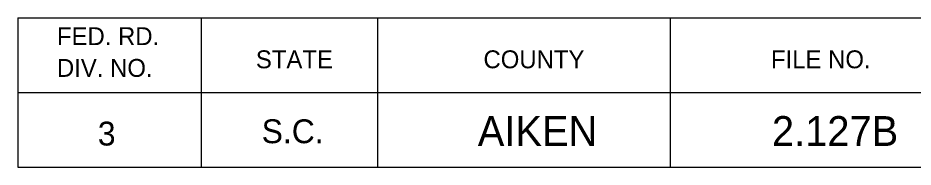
# Model space of a CAD drawing. Extents: x 1000 to 1162, y 999 to 8520.
# Drawn here: x 1133.06 to 1148.08, y 4895.05 to 4897.55 of the extents above; entities that cross this region are included whole.
import ezdxf

# ---------------------------------------------------------------- set-up
doc = ezdxf.new("R2010")
doc.units = 0
doc.layers.add('Level 20', color=7, linetype='Continuous')
doc.layers.add('Level 3', color=7, linetype='Continuous')

msp = doc.modelspace()

# ---------------------------------------------------------------- linework, layer by layer
at = {"layer": 'Level 3'}
for p, q in [((1133.055, 4897.546), (1161.555, 4897.546)), ((1133.055, 4897.546), (1133.055, 4895.046)), ((1133.055, 4897.546), (1161.555, 4897.546)), ((1133.055, 4897.546), (1133.055, 4895.046)), ((1133.055, 4897.546), (1161.555, 4897.546)), ((1133.055, 4897.546), (1133.055, 4895.046)), ((1133.055, 4897.546), (1161.555, 4897.546)), ((1133.055, 4897.546), (1133.055, 4895.046)), ((1133.055, 4897.546), (1161.555, 4897.546)), ((1133.055, 4897.546), (1133.055, 4895.046)), ((1133.055, 4897.546), (1161.555, 4897.546)), ((1133.055, 4897.546), (1133.055, 4895.046)), ((1133.055, 4897.546), (1161.555, 4897.546)), ((1133.055, 4897.546), (1133.055, 4895.046)), ((1133.055, 4897.546), (1161.555, 4897.546)), ((1133.055, 4897.546), (1133.055, 4895.046)), ((1133.055, 4897.546), (1161.555, 4897.546)), ((1133.055, 4897.546), (1133.055, 4895.046)), ((1133.055, 4897.546), (1161.555, 4897.546)), ((1133.055, 4897.546), (1133.055, 4895.046)), ((1133.055, 4897.546), (1161.555, 4897.546)), ((1133.055, 4897.546), (1133.055, 4895.046)), ((1133.055, 4897.546), (1161.555, 4897.546)), ((1133.055, 4897.546), (1133.055, 4895.046)), ((1133.055, 4897.546), (1161.555, 4897.546)), ((1133.055, 4897.546), (1133.055, 4895.046)), ((1133.055, 4897.546), (1161.555, 4897.546)), ((1133.055, 4897.546), (1133.055, 4895.046)), ((1133.055, 4897.546), (1161.555, 4897.546)), ((1133.055, 4897.546), (1133.055, 4895.046)), ((1133.055, 4897.546), (1161.555, 4897.546)), ((1133.055, 4897.546), (1133.055, 4895.046)), ((1133.055, 4897.546), (1161.555, 4897.546)), ((1133.055, 4897.546), (1133.055, 4895.046)), ((1133.055, 4897.546), (1161.555, 4897.546)), ((1133.055, 4897.546), (1133.055, 4895.046)), ((1133.055, 4897.546), (1161.555, 4897.546)), ((1133.055, 4897.546), (1133.055, 4895.046)), ((1133.055, 4897.546), (1161.555, 4897.546)), ((1133.055, 4897.546), (1133.055, 4895.046)), ((1133.055, 4897.546), (1161.555, 4897.546)), ((1133.055, 4897.546), (1133.055, 4895.046)), ((1133.055, 4897.546), (1161.555, 4897.546)), ((1133.055, 4897.546), (1133.055, 4895.046)), ((1133.055, 4897.546), (1161.555, 4897.546)), ((1133.055, 4897.546), (1133.055, 4895.046)), ((1133.055, 4897.546), (1161.555, 4897.546)), ((1133.055, 4897.546), (1133.055, 4895.046)), ((1133.055, 4897.546), (1161.555, 4897.546)), ((1133.055, 4897.546), (1133.055, 4895.046)), ((1133.055, 4897.546), (1161.555, 4897.546)), ((1133.055, 4897.546), (1133.055, 4895.046)), ((1133.055, 4897.546), (1161.555, 4897.546)), ((1133.055, 4897.546), (1133.055, 4895.046)), ((1133.055, 4897.546), (1161.555, 4897.546)), ((1133.055, 4897.546), (1133.055, 4895.046)), ((1133.055, 4897.546), (1161.555, 4897.546)), ((1133.055, 4897.546), (1133.055, 4895.046)), ((1133.055, 4897.546), (1161.555, 4897.546)), ((1133.055, 4897.546), (1133.055, 4895.046)), ((1133.055, 4897.546), (1161.555, 4897.546)), ((1133.055, 4897.546), (1133.055, 4895.046)), ((1133.055, 4897.546), (1161.555, 4897.546)), ((1133.055, 4897.546), (1133.055, 4895.046)), ((1136.132, 4897.546), (1136.132, 4895.046)), ((1136.132, 4897.546), (1136.132, 4895.046)), ((1136.132, 4897.546), (1136.132, 4895.046)), ((1136.132, 4897.546), (1136.132, 4895.046)), ((1136.132, 4897.546), (1136.132, 4895.046)), ((1136.132, 4897.546), (1136.132, 4895.046)), ((1136.132, 4897.546), (1136.132, 4895.046)), ((1136.132, 4897.546), (1136.132, 4895.046)), ((1136.132, 4897.546), (1136.132, 4895.046)), ((1136.132, 4897.546), (1136.132, 4895.046)), ((1136.132, 4897.546), (1136.132, 4895.046)), ((1136.132, 4897.546), (1136.132, 4895.046)), ((1136.132, 4897.546), (1136.132, 4895.046)), ((1136.132, 4897.546), (1136.132, 4895.046)), ((1136.132, 4897.546), (1136.132, 4895.046)), ((1136.132, 4897.546), (1136.132, 4895.046)), ((1136.132, 4897.546), (1136.132, 4895.046)), ((1136.132, 4897.546), (1136.132, 4895.046)), ((1136.132, 4897.546), (1136.132, 4895.046)), ((1136.132, 4897.546), (1136.132, 4895.046)), ((1136.132, 4897.546), (1136.132, 4895.046)), ((1136.132, 4897.546), (1136.132, 4895.046)), ((1136.132, 4897.546), (1136.132, 4895.046)), ((1136.132, 4897.546), (1136.132, 4895.046)), ((1136.132, 4897.546), (1136.132, 4895.046)), ((1136.132, 4897.546), (1136.132, 4895.046)), ((1136.132, 4897.546), (1136.132, 4895.046)), ((1136.132, 4897.546), (1136.132, 4895.046)), ((1136.132, 4897.546), (1136.132, 4895.046)), ((1136.132, 4897.546), (1136.132, 4895.046)), ((1136.132, 4897.546), (1136.132, 4895.046)), ((1136.132, 4897.546), (1136.132, 4895.046)), ((1139.087, 4897.546), (1139.087, 4895.046)), ((1139.087, 4897.546), (1139.087, 4895.046)), ((1139.087, 4897.546), (1139.087, 4895.046)), ((1139.087, 4897.546), (1139.087, 4895.046)), ((1139.087, 4897.546), (1139.087, 4895.046)), ((1139.087, 4897.546), (1139.087, 4895.046)), ((1139.087, 4897.546), (1139.087, 4895.046)), ((1139.087, 4897.546), (1139.087, 4895.046)), ((1139.087, 4897.546), (1139.087, 4895.046)), ((1139.087, 4897.546), (1139.087, 4895.046)), ((1139.087, 4897.546), (1139.087, 4895.046)), ((1139.087, 4897.546), (1139.087, 4895.046)), ((1139.087, 4897.546), (1139.087, 4895.046)), ((1139.087, 4897.546), (1139.087, 4895.046)), ((1139.087, 4897.546), (1139.087, 4895.046)), ((1139.087, 4897.546), (1139.087, 4895.046)), ((1139.087, 4897.546), (1139.087, 4895.046)), ((1139.087, 4897.546), (1139.087, 4895.046)), ((1139.087, 4897.546), (1139.087, 4895.046)), ((1139.087, 4897.546), (1139.087, 4895.046)), ((1139.087, 4897.546), (1139.087, 4895.046)), ((1139.087, 4897.546), (1139.087, 4895.046)), ((1139.087, 4897.546), (1139.087, 4895.046)), ((1139.087, 4897.546), (1139.087, 4895.046)), ((1139.087, 4897.546), (1139.087, 4895.046)), ((1139.087, 4897.546), (1139.087, 4895.046)), ((1139.087, 4897.546), (1139.087, 4895.046)), ((1139.087, 4897.546), (1139.087, 4895.046)), ((1139.087, 4897.546), (1139.087, 4895.046)), ((1139.087, 4897.546), (1139.087, 4895.046)), ((1139.087, 4897.546), (1139.087, 4895.046)), ((1139.087, 4897.546), (1139.087, 4895.046)), ((1144, 4897.546), (1144, 4895.046)), ((1144, 4897.546), (1144, 4895.046)), ((1144, 4897.546), (1144, 4895.046)), ((1144, 4897.546), (1144, 4895.046)), ((1144, 4897.546), (1144, 4895.046)), ((1144, 4897.546), (1144, 4895.046)), ((1144, 4897.546), (1144, 4895.046)), ((1144, 4897.546), (1144, 4895.046)), ((1144, 4897.546), (1144, 4895.046)), ((1144, 4897.546), (1144, 4895.046)), ((1144, 4897.546), (1144, 4895.046)), ((1144, 4897.546), (1144, 4895.046)), ((1144, 4897.546), (1144, 4895.046)), ((1144, 4897.546), (1144, 4895.046)), ((1144, 4897.546), (1144, 4895.046)), ((1144, 4897.546), (1144, 4895.046)), ((1144, 4897.546), (1144, 4895.046)), ((1144, 4897.546), (1144, 4895.046)), ((1144, 4897.546), (1144, 4895.046)), ((1144, 4897.546), (1144, 4895.046)), ((1144, 4897.546), (1144, 4895.046)), ((1144, 4897.546), (1144, 4895.046)), ((1144, 4897.546), (1144, 4895.046)), ((1144, 4897.546), (1144, 4895.046)), ((1144, 4897.546), (1144, 4895.046)), ((1144, 4897.546), (1144, 4895.046)), ((1144, 4897.546), (1144, 4895.046)), ((1144, 4897.546), (1144, 4895.046)), ((1144, 4897.546), (1144, 4895.046)), ((1144, 4897.546), (1144, 4895.046)), ((1144, 4897.546), (1144, 4895.046)), ((1144, 4897.546), (1144, 4895.046)), ((1133.055, 4896.296), (1161.555, 4896.296)), ((1133.055, 4896.296), (1161.555, 4896.296)), ((1133.055, 4896.296), (1161.555, 4896.296)), ((1133.055, 4896.296), (1161.555, 4896.296)), ((1133.055, 4896.296), (1161.555, 4896.296)), ((1133.055, 4896.296), (1161.555, 4896.296)), ((1133.055, 4896.296), (1161.555, 4896.296)), ((1133.055, 4896.296), (1161.555, 4896.296)), ((1133.055, 4896.296), (1161.555, 4896.296)), ((1133.055, 4896.296), (1161.555, 4896.296)), ((1133.055, 4896.296), (1161.555, 4896.296)), ((1133.055, 4896.296), (1161.555, 4896.296)), ((1133.055, 4896.296), (1161.555, 4896.296)), ((1133.055, 4896.296), (1161.555, 4896.296)), ((1133.055, 4896.296), (1161.555, 4896.296)), ((1133.055, 4896.296), (1161.555, 4896.296)), ((1133.055, 4896.296), (1161.555, 4896.296)), ((1133.055, 4896.296), (1161.555, 4896.296)), ((1133.055, 4896.296), (1161.555, 4896.296)), ((1133.055, 4896.296), (1161.555, 4896.296)), ((1133.055, 4896.296), (1161.555, 4896.296)), ((1133.055, 4896.296), (1161.555, 4896.296)), ((1133.055, 4896.296), (1161.555, 4896.296)), ((1133.055, 4896.296), (1161.555, 4896.296)), ((1133.055, 4896.296), (1161.555, 4896.296)), ((1133.055, 4896.296), (1161.555, 4896.296)), ((1133.055, 4896.296), (1161.555, 4896.296)), ((1133.055, 4896.296), (1161.555, 4896.296)), ((1133.055, 4896.296), (1161.555, 4896.296)), ((1133.055, 4896.296), (1161.555, 4896.296)), ((1133.055, 4896.296), (1161.555, 4896.296)), ((1133.055, 4896.296), (1161.555, 4896.296)), ((1133.055, 4895.046), (1161.555, 4895.046)), ((1133.055, 4895.046), (1161.555, 4895.046)), ((1133.055, 4895.046), (1161.555, 4895.046)), ((1133.055, 4895.046), (1161.555, 4895.046)), ((1133.055, 4895.046), (1161.555, 4895.046)), ((1133.055, 4895.046), (1161.555, 4895.046)), ((1133.055, 4895.046), (1161.555, 4895.046)), ((1133.055, 4895.046), (1161.555, 4895.046)), ((1133.055, 4895.046), (1161.555, 4895.046)), ((1133.055, 4895.046), (1161.555, 4895.046)), ((1133.055, 4895.046), (1161.555, 4895.046)), ((1133.055, 4895.046), (1161.555, 4895.046)), ((1133.055, 4895.046), (1161.555, 4895.046)), ((1133.055, 4895.046), (1161.555, 4895.046)), ((1133.055, 4895.046), (1161.555, 4895.046)), ((1133.055, 4895.046), (1161.555, 4895.046)), ((1133.055, 4895.046), (1161.555, 4895.046)), ((1133.055, 4895.046), (1161.555, 4895.046)), ((1133.055, 4895.046), (1161.555, 4895.046)), ((1133.055, 4895.046), (1161.555, 4895.046)), ((1133.055, 4895.046), (1161.555, 4895.046)), ((1133.055, 4895.046), (1161.555, 4895.046)), ((1133.055, 4895.046), (1161.555, 4895.046)), ((1133.055, 4895.046), (1161.555, 4895.046)), ((1133.055, 4895.046), (1161.555, 4895.046)), ((1133.055, 4895.046), (1161.555, 4895.046)), ((1133.055, 4895.046), (1161.555, 4895.046)), ((1133.055, 4895.046), (1161.555, 4895.046)), ((1133.055, 4895.046), (1161.555, 4895.046)), ((1133.055, 4895.046), (1161.555, 4895.046)), ((1133.055, 4895.046), (1161.555, 4895.046)), ((1133.055, 4895.046), (1161.555, 4895.046))]:
    msp.add_line(p, q, dxfattribs=at)

# ---------------------------------------------------------------- texts
at = {"layer": 'Level 20'}
for s, p in [('AIKEN', (1140.771, 4895.4)), ('2.127B', (1145.707, 4895.4))]:
    msp.add_text(s, height=0.5, dxfattribs=at).set_placement(p)
at = {"layer": 'Level 3'}
for s, height, p in [('FED. RD.', 0.3, (1133.71, 4897.09)), ('FED. RD.', 0.3, (1133.71, 4897.09)), ('FED. RD.', 0.3, (1133.71, 4897.09)), ('FED. RD.', 0.3, (1133.71, 4897.09)), ('FED. RD.', 0.3, (1133.71, 4897.09)), ('FED. RD.', 0.3, (1133.71, 4897.09)), ('FED. RD.', 0.3, (1133.71, 4897.09)), ('FED. RD.', 0.3, (1133.71, 4897.09)), ('FED. RD.', 0.3, (1133.71, 4897.09)), ('FED. RD.', 0.3, (1133.71, 4897.09)), ('FED. RD.', 0.3, (1133.71, 4897.09)), ('FED. RD.', 0.3, (1133.71, 4897.09)), ('FED. RD.', 0.3, (1133.71, 4897.09)), ('FED. RD.', 0.3, (1133.71, 4897.09)), ('FED. RD.', 0.3, (1133.71, 4897.09)), ('FED. RD.', 0.3, (1133.71, 4897.09)), ('FED. RD.', 0.3, (1133.71, 4897.09)), ('FED. RD.', 0.3, (1133.71, 4897.09)), ('FED. RD.', 0.3, (1133.71, 4897.09)), ('FED. RD.', 0.3, (1133.71, 4897.09)), ('FED. RD.', 0.3, (1133.71, 4897.09)), ('FED. RD.', 0.3, (1133.71, 4897.09)), ('FED. RD.', 0.3, (1133.71, 4897.09)), ('FED. RD.', 0.3, (1133.71, 4897.09)), ('FED. RD.', 0.3, (1133.71, 4897.09)), ('FED. RD.', 0.3, (1133.71, 4897.09)), ('FED. RD.', 0.3, (1133.71, 4897.09)), ('FED. RD.', 0.3, (1133.71, 4897.09)), ('FED. RD.', 0.3, (1133.71, 4897.09)), ('FED. RD.', 0.3, (1133.71, 4897.09)), ('FED. RD.', 0.3, (1133.71, 4897.09)), ('FED. RD.', 0.3, (1133.71, 4897.09)), ('STATE', 0.3, (1137.048, 4896.702)), ('STATE', 0.3, (1137.048, 4896.702)), ('STATE', 0.3, (1137.048, 4896.702)), ('STATE', 0.3, (1137.048, 4896.702)), ('STATE', 0.3, (1137.048, 4896.702)), ('STATE', 0.3, (1137.048, 4896.702)), ('STATE', 0.3, (1137.048, 4896.702)), ('STATE', 0.3, (1137.048, 4896.702)), ('STATE', 0.3, (1137.048, 4896.702)), ('STATE', 0.3, (1137.048, 4896.702)), ('STATE', 0.3, (1137.048, 4896.702)), ('STATE', 0.3, (1137.048, 4896.702)), ('STATE', 0.3, (1137.048, 4896.702)), ('STATE', 0.3, (1137.048, 4896.702)), ('STATE', 0.3, (1137.048, 4896.702)), ('STATE', 0.3, (1137.048, 4896.702)), ('STATE', 0.3, (1137.048, 4896.702)), ('STATE', 0.3, (1137.048, 4896.702)), ('STATE', 0.3, (1137.048, 4896.702)), ('STATE', 0.3, (1137.048, 4896.702)), ('STATE', 0.3, (1137.048, 4896.702)), ('STATE', 0.3, (1137.048, 4896.702)), ('STATE', 0.3, (1137.048, 4896.702)), ('STATE', 0.3, (1137.048, 4896.702)), ('STATE', 0.3, (1137.048, 4896.702)), ('STATE', 0.3, (1137.048, 4896.702)), ('STATE', 0.3, (1137.048, 4896.702)), ('STATE', 0.3, (1137.048, 4896.702)), ('STATE', 0.3, (1137.048, 4896.702)), ('STATE', 0.3, (1137.048, 4896.702)), ('STATE', 0.3, (1137.048, 4896.702)), ('STATE', 0.3, (1137.048, 4896.702)), ('COUNTY', 0.3, (1140.867, 4896.702)), ('COUNTY', 0.3, (1140.867, 4896.702)), ('COUNTY', 0.3, (1140.867, 4896.702)), ('COUNTY', 0.3, (1140.867, 4896.702)), ('COUNTY', 0.3, (1140.867, 4896.702)), ('COUNTY', 0.3, (1140.867, 4896.702)), ('COUNTY', 0.3, (1140.867, 4896.702)), ('COUNTY', 0.3, (1140.867, 4896.702)), ('COUNTY', 0.3, (1140.867, 4896.702)), ('COUNTY', 0.3, (1140.867, 4896.702)), ('COUNTY', 0.3, (1140.867, 4896.702)), ('COUNTY', 0.3, (1140.867, 4896.702)), ('COUNTY', 0.3, (1140.867, 4896.702)), ('COUNTY', 0.3, (1140.867, 4896.702)), ('COUNTY', 0.3, (1140.867, 4896.702)), ('COUNTY', 0.3, (1140.867, 4896.702)), ('COUNTY', 0.3, (1140.867, 4896.702)), ('COUNTY', 0.3, (1140.867, 4896.702)), ('COUNTY', 0.3, (1140.867, 4896.702)), ('COUNTY', 0.3, (1140.867, 4896.702)), ('COUNTY', 0.3, (1140.867, 4896.702)), ('COUNTY', 0.3, (1140.867, 4896.702)), ('COUNTY', 0.3, (1140.867, 4896.702)), ('COUNTY', 0.3, (1140.867, 4896.702)), ('COUNTY', 0.3, (1140.867, 4896.702)), ('COUNTY', 0.3, (1140.867, 4896.702)), ('COUNTY', 0.3, (1140.867, 4896.702)), ('COUNTY', 0.3, (1140.867, 4896.702)), ('COUNTY', 0.3, (1140.867, 4896.702)), ('COUNTY', 0.3, (1140.867, 4896.702)), ('COUNTY', 0.3, (1140.867, 4896.702)), ('COUNTY', 0.3, (1140.867, 4896.702)), ('FILE NO.', 0.3, (1145.691, 4896.702)), ('FILE NO.', 0.3, (1145.691, 4896.702)), ('FILE NO.', 0.3, (1145.691, 4896.702)), ('FILE NO.', 0.3, (1145.691, 4896.702)), ('FILE NO.', 0.3, (1145.691, 4896.702)), ('FILE NO.', 0.3, (1145.691, 4896.702)), ('FILE NO.', 0.3, (1145.691, 4896.702)), ('FILE NO.', 0.3, (1145.691, 4896.702)), ('FILE NO.', 0.3, (1145.691, 4896.702)), ('FILE NO.', 0.3, (1145.691, 4896.702)), ('FILE NO.', 0.3, (1145.691, 4896.702)), ('FILE NO.', 0.3, (1145.691, 4896.702)), ('FILE NO.', 0.3, (1145.691, 4896.702)), ('FILE NO.', 0.3, (1145.691, 4896.702)), ('FILE NO.', 0.3, (1145.691, 4896.702)), ('FILE NO.', 0.3, (1145.691, 4896.702)), ('FILE NO.', 0.3, (1145.691, 4896.702)), ('FILE NO.', 0.3, (1145.691, 4896.702)), ('FILE NO.', 0.3, (1145.691, 4896.702)), ('FILE NO.', 0.3, (1145.691, 4896.702)), ('FILE NO.', 0.3, (1145.691, 4896.702)), ('FILE NO.', 0.3, (1145.691, 4896.702)), ('FILE NO.', 0.3, (1145.691, 4896.702)), ('FILE NO.', 0.3, (1145.691, 4896.702)), ('FILE NO.', 0.3, (1145.691, 4896.702)), ('FILE NO.', 0.3, (1145.691, 4896.702)), ('FILE NO.', 0.3, (1145.691, 4896.702)), ('FILE NO.', 0.3, (1145.691, 4896.702)), ('FILE NO.', 0.3, (1145.691, 4896.702)), ('FILE NO.', 0.3, (1145.691, 4896.702)), ('FILE NO.', 0.3, (1145.691, 4896.702)), ('FILE NO.', 0.3, (1145.691, 4896.702)), ('DIV. NO.', 0.3, (1133.71, 4896.558)), ('DIV. NO.', 0.3, (1133.71, 4896.558)), ('DIV. NO.', 0.3, (1133.71, 4896.558)), ('DIV. NO.', 0.3, (1133.71, 4896.558)), ('DIV. NO.', 0.3, (1133.71, 4896.558)), ('DIV. NO.', 0.3, (1133.71, 4896.558)), ('DIV. NO.', 0.3, (1133.71, 4896.558)), ('DIV. NO.', 0.3, (1133.71, 4896.558)), ('DIV. NO.', 0.3, (1133.71, 4896.558)), ('DIV. NO.', 0.3, (1133.71, 4896.558)), ('DIV. NO.', 0.3, (1133.71, 4896.558)), ('DIV. NO.', 0.3, (1133.71, 4896.558)), ('DIV. NO.', 0.3, (1133.71, 4896.558)), ('DIV. NO.', 0.3, (1133.71, 4896.558)), ('DIV. NO.', 0.3, (1133.71, 4896.558)), ('DIV. NO.', 0.3, (1133.71, 4896.558)), ('DIV. NO.', 0.3, (1133.71, 4896.558)), ('DIV. NO.', 0.3, (1133.71, 4896.558)), ('DIV. NO.', 0.3, (1133.71, 4896.558)), ('DIV. NO.', 0.3, (1133.71, 4896.558)), ('DIV. NO.', 0.3, (1133.71, 4896.558)), ('DIV. NO.', 0.3, (1133.71, 4896.558)), ('DIV. NO.', 0.3, (1133.71, 4896.558)), ('DIV. NO.', 0.3, (1133.71, 4896.558)), ('DIV. NO.', 0.3, (1133.71, 4896.558)), ('DIV. NO.', 0.3, (1133.71, 4896.558)), ('DIV. NO.', 0.3, (1133.71, 4896.558)), ('DIV. NO.', 0.3, (1133.71, 4896.558)), ('DIV. NO.', 0.3, (1133.71, 4896.558)), ('DIV. NO.', 0.3, (1133.71, 4896.558)), ('DIV. NO.', 0.3, (1133.71, 4896.558)), ('DIV. NO.', 0.3, (1133.71, 4896.558)), ('S.C.', 0.4, (1137.145, 4895.446)), ('S.C.', 0.4, (1137.145, 4895.446)), ('S.C.', 0.4, (1137.145, 4895.446)), ('S.C.', 0.4, (1137.145, 4895.446)), ('S.C.', 0.4, (1137.145, 4895.446)), ('S.C.', 0.4, (1137.145, 4895.446)), ('S.C.', 0.4, (1137.145, 4895.446)), ('S.C.', 0.4, (1137.145, 4895.446)), ('S.C.', 0.4, (1137.145, 4895.446)), ('S.C.', 0.4, (1137.145, 4895.446)), ('S.C.', 0.4, (1137.145, 4895.446)), ('S.C.', 0.4, (1137.145, 4895.446)), ('S.C.', 0.4, (1137.145, 4895.446)), ('S.C.', 0.4, (1137.145, 4895.446)), ('S.C.', 0.4, (1137.145, 4895.446)), ('S.C.', 0.4, (1137.145, 4895.446)), ('S.C.', 0.4, (1137.145, 4895.446)), ('S.C.', 0.4, (1137.145, 4895.446)), ('S.C.', 0.4, (1137.145, 4895.446)), ('S.C.', 0.4, (1137.145, 4895.446)), ('S.C.', 0.4, (1137.145, 4895.446)), ('S.C.', 0.4, (1137.145, 4895.446)), ('S.C.', 0.4, (1137.145, 4895.446)), ('S.C.', 0.4, (1137.145, 4895.446)), ('S.C.', 0.4, (1137.145, 4895.446)), ('S.C.', 0.4, (1137.145, 4895.446)), ('S.C.', 0.4, (1137.145, 4895.446)), ('S.C.', 0.4, (1137.145, 4895.446)), ('S.C.', 0.4, (1137.145, 4895.446)), ('S.C.', 0.4, (1137.145, 4895.446)), ('S.C.', 0.4, (1137.145, 4895.446)), ('S.C.', 0.4, (1137.145, 4895.446)), ('3', 0.4, (1134.396, 4895.407)), ('3', 0.4, (1134.396, 4895.407)), ('3', 0.4, (1134.396, 4895.407)), ('3', 0.4, (1134.396, 4895.407)), ('3', 0.4, (1134.396, 4895.407)), ('3', 0.4, (1134.396, 4895.407)), ('3', 0.4, (1134.396, 4895.407)), ('3', 0.4, (1134.396, 4895.407)), ('3', 0.4, (1134.396, 4895.407)), ('3', 0.4, (1134.396, 4895.407)), ('3', 0.4, (1134.396, 4895.407)), ('3', 0.4, (1134.396, 4895.407)), ('3', 0.4, (1134.396, 4895.407)), ('3', 0.4, (1134.396, 4895.407)), ('3', 0.4, (1134.396, 4895.407)), ('3', 0.4, (1134.396, 4895.407)), ('3', 0.4, (1134.396, 4895.407)), ('3', 0.4, (1134.396, 4895.407)), ('3', 0.4, (1134.396, 4895.407)), ('3', 0.4, (1134.396, 4895.407)), ('3', 0.4, (1134.396, 4895.407)), ('3', 0.4, (1134.396, 4895.407)), ('3', 0.4, (1134.396, 4895.407)), ('3', 0.4, (1134.396, 4895.407)), ('3', 0.4, (1134.396, 4895.407)), ('3', 0.4, (1134.396, 4895.407)), ('3', 0.4, (1134.396, 4895.407)), ('3', 0.4, (1134.396, 4895.407)), ('3', 0.4, (1134.396, 4895.407)), ('3', 0.4, (1134.396, 4895.407)), ('3', 0.4, (1134.396, 4895.407)), ('3', 0.4, (1134.396, 4895.407))]:
    msp.add_text(s, height=height, dxfattribs=at).set_placement(p)

doc.saveas('drawing.dxf')
